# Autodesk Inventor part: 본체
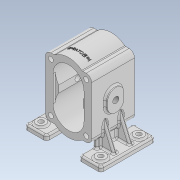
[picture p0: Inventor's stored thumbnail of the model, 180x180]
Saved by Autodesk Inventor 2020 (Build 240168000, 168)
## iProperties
Created: 2023-06
Part Number: 본체
Material: 일반
Document SubType Name: Modeling
Designer: oem
Density: 1 g/cm^3
Appearance: 기본값
Author: oem
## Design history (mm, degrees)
sketch "스케치1"
  geometry: L1 (-32.5, 55)-(32.5, 55); L2 (42.5, 45)-(42.5, -45); L3 (32.5, -55)-(-32.5, -55); L4 (-42.5, -45)-(-42.5, 45); L5 (-42.5, 55)-(42.5, -55); L6 (42.5, 55)-(-42.5, -55); L7 (-32.5, 45)-(32.5, 45); L8 (32.5, 45)-(32.5, -45); L9 (32.5, -45)-(-32.5, -45); L10 (-32.5, -45)-(-32.5, 45); L11 (-32.5, 45)-(32.5, -45); L12 (32.5, 45)-(-32.5, -45); C1 r 4.5 at (-32.5, 45); C2 r 4.5 at (32.5, 45); C3 r 4.5 at (32.5, -45); C4 r 4.5 at (-32.5, -45); A1 r 10 centre (-32.5, 45) between (-32.5, 55) and (-42.5, 45); A2 r 10 centre (32.5, 45) between (42.5, 45) and (32.5, 55); A3 r 10 centre (32.5, -45) between (32.5, -55) and (42.5, -45); A4 r 10 centre (-32.5, -45) between (-42.5, -45) and (-32.5, -55); 1 further point
  constraints: 24 end point, 8 centre point, 8 point on circle, 8 point on line, 8 tangent, 4 coincident, 4 midpoint, 4 parallel, 3 equal radius, 2 horizontal, 2 perpendicular
  dimensions: "d0" = 85 distance of L5.end L6.end; "d1" = 110 distance of L6.start L5.end; "d2" = 10 radius of A1; "d3" = 65 distance of L8.end L9.end; "d4" = 90 distance of L7.end L8.end; "d5" = 9 diameter of C1; "d6" = 9 diameter of C2; "d7" = 9 diameter of C3; "d8" = 9 diameter of C4
extrude "돌출1" new body sketch "스케치1" distance "d9" = 79; taper "d10" = 0 deg
sketch "스케치2"
  geometry: L1 (32.5, 55)-(-32.5, 55) reference; A1 r 40 centre (0, 24) between (-25.278, 55) and (25.278, 55); A2 r 40 centre (0, 24) between (25.278, 55) and (-25.278, 55); 1 further point
  constraints: 4 point on circle, 2 centre point, 2 point on line, 1 vertical alignment
  dimensions: "d11" = 80 diameter of A1; "d12" = 24 distance of point (0, 0) A1.centre
extrude "돌출2" join sketch "스케치2" distance "d13" = 79; taper "d14" = 0 deg
node "작업 평면1"
sketch "스케치3"
  geometry: L1 (-42.5, 0)-(-42.5, 79) reference; L2 (25.278, 79)-(-25.278, 79) reference; L3 (70, -10.5)-(30, -10.5); L4 (-70, -10.5)-(-70, 89.5); L5 (-70, 89.5)-(-30, 89.5); L6 (70, 89.5)-(70, -10.5); L7 (70, -10.5)-(-70, 89.5); L8 (-70, -10.5)-(70, 89.5); L9 (-30, -10.5)-(-30, 89.5); L10 (-30, -10.5)-(-70, -10.5); L11 (-30, 89.5)-(30, 89.5); L12 (30, -10.5)-(30, 89.5); L13 (30, -10.5)-(-30, -10.5); L14 (30, 89.5)-(70, 89.5); 6 further points
  constraints: 24 end point, 10 parallel, 8 perpendicular, 6 midpoint, 3 horizontal, 1 horizontal alignment, 1 vertical alignment
  dimensions: "d16" = 140 distance of L4.end L6.start; "d17" = 100 distance of L4.start L4.end; "d18" = 40 distance between parallel lines of L4 L9; "d19" = 40 distance between parallel lines of L12 L6
extrude "돌출3" join sketch "스케치3" distance "d20" = 9; taper "d21" = 0 deg
sketch "스케치4"
  geometry: L1 (30, 10.5)-(30, -89.5) reference; L2 (30, -14.5)-(38, -14.5); L3 (38, -14.5)-(38, -64.5); L4 (38, -64.5)-(30, -64.5); L5 (30, -64.5)-(30, -14.5); 3 further points
  constraints: 8 end point, 2 midpoint, 2 parallel, 1 horizontal, 1 perpendicular, 1 point on line
  dimensions: "d22" = 8 distance of L3.end L4.end; "d23" = 50 distance of L2.end L3.end
extrude "돌출4" join sketch "스케치4" stored distance "d24" = 9; taper "d25" = 0 deg
sketch "스케치5"
  geometry: L1 (0, 0)-(0, 90) reference; L2 (0, 0)-(-79, 0) reference; L3 (-39.5, 50)-(-39.5, 40); L4 (-54.5, 50)-(-54.5, 40); L5 (-24.5, 40)-(-24.5, 50); A1 r 15 centre (-39.5, 50) between (-24.5, 50) and (-54.5, 50); A2 r 15 centre (-39.5, 40) between (-54.5, 40) and (-24.5, 40); 5 further points
  constraints: 8 end point, 4 point on circle, 4 tangent, 3 midpoint, 2 centre point, 1 coincident, 1 horizontal alignment, 1 parallel, 1 vertical, 1 vertical alignment
  dimensions: "d26" = 30 diameter of A2; "d27" = 40 dimension on A2 A1
sketch "스케치6"
  geometry: L1 (70, -89.5)-(70, 10.5) reference; L2 (55, -4.5)-(55, -74.5); C1 r 9 at (55, -74.5); C2 r 9 at (55, -4.5); 3 further points
  constraints: 2 centre point, 2 end point, 2 midpoint, 1 horizontal alignment, 1 vertical, 1 vertical alignment
  dimensions: "d28" = 15 distance from line of L1 L2.end; "d29" = 18 diameter of C1; "d30" = 18 diameter of C2; "d31" = 70 distance of L2.start L2.end
extrude "돌출5" join sketch "스케치6" distance "d32" = 3; taper "d33" = 0 deg
sketch "스케치7"
  geometry: C1 r 9 at (0, 0) reference; C2 r 9 at (0, 70) reference; 3 further points
  constraints: 2 coincident
hole "구멍1" sketch "스케치7" at (0, 0), (0, 70) diameter "d34" = 9; stored, may be unused: countersink angle "d38" = 90 deg, drill point angle "d40" = 118 deg; dims "d35" = 6, "d36" = 4, "d37" = 2, "d39" = 8
node "작업 평면3"
  node "작업 평면2"
sketch "스케치8"
  geometry: L1 (70, -71)-(30, -71) reference; L2 (70, -80)-(70, -71) reference; L3 (42.5, -45)-(42.5, 45) reference; L4 (62, -71)-(39.578, -18.177); 1 further point
  constraints: 2 end point, 1 point on line
  dimensions: "d46" = 8 distance from line of L2 L4.start; "d47" = 23 deg angle of L2 L4
feature "리브1" sketch "스케치8" dims "d48" = 1, "d49" = 7, "d50" = 0, "d51" = 0, "d52" = 1, "d53" = 1
node "작업 평면4"
node "작업 평면5"
sketch "스케치9"
  geometry: L1 (70, -10.5)-(70, 89.5) reference; L2 (70, 39.5)-(-70, 39.5); L3 (-70, 89.5)-(-70, -10.5) reference; 2 further points
  constraints: 2 end point, 2 midpoint, 1 vertical alignment, 1 other
  dimensions: "d55" = 20 distance from line of point (0, 59.5) L2
feature "엠보싱1" sketch "스케치9" dims "d56" = 0.5, "d57" = 0
sketch "스케치10"
  geometry: L1 (-42.5, 45)-(-42.5, -45) reference; L2 (22.5, 6.507)-(22.5, -6.507); L3 (-22.5, -6.507)-(-22.5, 6.507); L4 (-22.5, 0)-(22.5, 0); A1 r 40 centre (0, -24) between (-25.278, -55) and (25.278, -55) reference; A2 r 28.5 centre (0, -24) between (-22.5, -6.507) and (22.5, -6.507); A3 r 40 centre (0, 24) between (1.526, 63.971) and (-2.042, 63.948) reference; A4 r 28.5 centre (0, 24) between (22.5, 6.507) and (-22.5, 6.507); 2 further points
  constraints: 6 end point, 4 midpoint, 4 point on circle, 2 centre point, 2 coincident, 1 horizontal alignment, 1 parallel
  dimensions: "d58" = 57 diameter of A2; "d59" = 57 diameter of A4; "d62" = 45 distance between parallel lines of L2 L3; "d63" = 42.5 distance from line of point (0, 0) L1
extrude "돌출6" cut sketch "스케치10" extent not by distance; stored distance "d64" = 0; taper "d65" = 0 deg
sketch "스케치12"
  geometry: L1 (45, 79)-(-45, 79) reference; L2 (24, 79)-(-24, 79); L3 (-24, 79)-(-24, 74.5); L4 (-24, 74.5)-(24, 74.5); L5 (24, 74.5)-(24, 79); 4 further points
  constraints: 8 end point, 2 midpoint, 2 parallel, 1 horizontal, 1 perpendicular, 1 point on line, 1 vertical alignment
  dimensions: "d66" = 48 distance of L4.end L3.end; "d67" = 4.5 distance of L2.end L3.end
extrude "돌출7" cut sketch "스케치12" stored distance "d68" = 57; taper "d69" = 0 deg
node "작업 평면6"
fillet "모깎기1" dims "d70" = 5
fillet "모깎기2" dims "d71" = 3
fillet "모깎기3" dims "d72" = 3
fillet "모깎기6" dims "d75" = 3
fillet "모깎기7" dims "d76" = 3
fillet "모깎기8" dims "d77" = 3
fillet "모깎기9" dims "d78" = 3
fillet "모깎기10" dims "d79" = 3
fillet "모깎기11" dims "d80" = 3
fillet "모깎기12" dims "d81" = 3
fillet "모깎기13" dims "d82" = 3
fillet "모깎기14" dims "d83" = 3
extrude "돌출8" join sketch "스케치5" distance "d84" = 5; taper "d85" = 0 deg
sketch "스케치13"
  geometry: L1 (-24.5, 40)-(-24.5, 50) reference; A1 r 15 centre (-39.5, 50) between (-24.5, 50) and (-54.5, 50) reference; 3 further points
  constraints: 1 horizontal alignment, 1 midpoint, 1 vertical alignment
hole "구멍2" sketch "스케치13" at (-39.5, 45) diameter "d86" = 10.5; stored, may be unused: countersink angle "d92" = 90 deg, drill point angle "d94" = 118 deg; dims "d87" = 11, "d88" = 0.62479, "d89" = 10.589, "d90" = 4, "d91" = 2, "d93" = 17.5
fillet "모깎기15" dims "d95" = 3
fillet "모깎기16" dims "d96" = 3
fillet "모깎기17" dims "d97" = 3
node "솔리드1"
mirror "미러1"
mirror "미러2"
mirror "미러3"
mirror "미러4"
mirror "미러5"
mirror "미러6"
mirror "미러8"
mirror "미러9"
feature "A9D066F2-1C7D-4E18-AEED-F7BC21143FA4" dims "d34" = 9, "d35" = 6, "d36" = 4, "d37" = 2, "d38" = 90 deg, "d39" = 8, "d40" = 118 deg
other parameters: "d41" = 11
